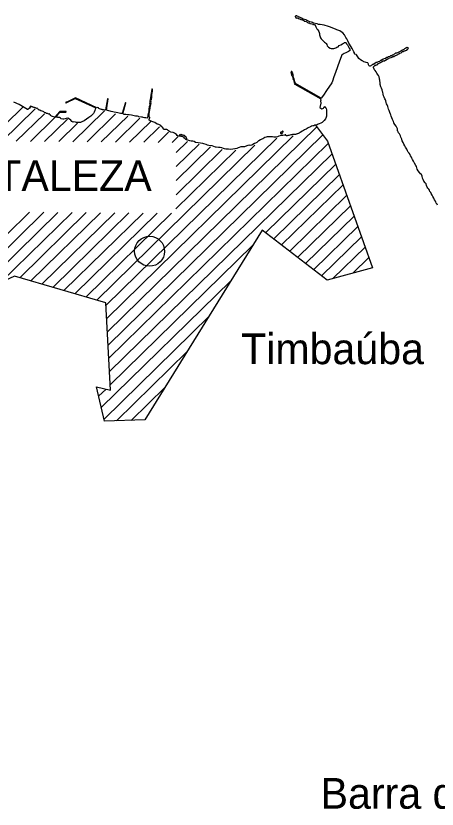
# Model space of a CAD drawing. Extents: x 662444 to 1640468, y 7452018 to 9606170.
# Drawn here: x 1219061 to 1228458, y 9570800 to 9588518 of the extents above; entities that cross this region are included whole.
import ezdxf

# ---------------------------------------------------------------- set-up
doc = ezdxf.new("R2010")
doc.units = 0
for name, color, linetype in [('Level 1', 7, 'Continuous'), ('Level 2', 7, 'Continuous'), ('Level 3', 7, 'Continuous')]:
    doc.layers.add(name, color=color, linetype=linetype)

msp = doc.modelspace()

# ---------------------------------------------------------------- linework, layer by layer
at = {"layer": 'Level 1'}
for points in [[(1225745, 9586079), (1226012, 9585722), (1227015, 9582889), (1226007, 9582614), (1224558, 9583735), (1221937, 9579492), (1221037, 9579467), (1220858, 9580229), (1221173, 9580161), (1221071, 9582105), (1219032, 9582704), (1218218, 9582331), (1216260, 9583731), (1213112, 9582624), (1212367, 9583519), (1212654, 9583962), (1212769, 9587547), (1215230, 9588504)], [(1227631, 9587725), (1227604, 9587708), (1227587, 9587700), (1227574, 9587695), (1227550, 9587683), (1227529, 9587682), (1227516, 9587668), (1227500, 9587662), (1227480, 9587643), (1227460, 9587642), (1227440, 9587625), (1227419, 9587624), (1227402, 9587608), (1227374, 9587603), (1227351, 9587588), (1227334, 9587587), (1227305, 9587567), (1227272, 9587560), (1227264, 9587548), (1227236, 9587541), (1227209, 9587524), (1227197, 9587521), (1227169, 9587500), (1227143, 9587495), (1227114, 9587476), (1227092, 9587473), (1227068, 9587454), (1227053, 9587454), (1227037, 9587435), (1227013, 9587432), (1227003, 9587418), (1226987, 9587406), (1226976, 9587405), (1226964, 9587396), (1226958, 9587398), (1226944, 9587400), (1226935, 9587413), (1226930, 9587427), (1226927, 9587441), (1226921, 9587452), (1226909, 9587466), (1226872, 9587478), (1226851, 9587484), (1226826, 9587489), (1226813, 9587497), (1226786, 9587511), (1226751, 9587533), (1226712, 9587564), (1226688, 9587604), (1226674, 9587629), (1226662, 9587648), (1226649, 9587658), (1226621, 9587666), (1226617, 9587672), (1226612, 9587693), (1226599, 9587714), (1226584, 9587746), (1226562, 9587788), (1226544, 9587827), (1226489, 9587909), (1226466, 9587960), (1226447, 9588002), (1226420, 9588033), (1226409, 9588064), (1226391, 9588094), (1226356, 9588140), (1226317, 9588165), (1226284, 9588185), (1226220, 9588210), (1226190, 9588219), (1226135, 9588244), (1226083, 9588268), (1226038, 9588283), (1225939, 9588312), (1225852, 9588327), (1225814, 9588329), (1225781, 9588337), (1225703, 9588356), (1225676, 9588368), (1225653, 9588376), (1225618, 9588388), (1225575, 9588406), (1225553, 9588416), (1225528, 9588429), (1225500, 9588440), (1225472, 9588446), (1225433, 9588467), (1225415, 9588471), (1225391, 9588490), (1225372, 9588493), (1225356, 9588506), (1225338, 9588508), (1225326, 9588517), (1225315, 9588516), (1225309, 9588518), (1225297, 9588515), (1225298, 9588512), (1225291, 9588507), (1225291, 9588500), (1225295, 9588498), (1225295, 9588486)], [(1225295, 9588486), (1225301, 9588486), (1225308, 9588476), (1225318, 9588478), (1225330, 9588470), (1225344, 9588471), (1225364, 9588457), (1225386, 9588454), (1225401, 9588443), (1225408, 9588443), (1225421, 9588435), (1225427, 9588436), (1225445, 9588427), (1225456, 9588428), (1225469, 9588423), (1225482, 9588415), (1225495, 9588401), (1225506, 9588400), (1225533, 9588389), (1225551, 9588383), (1225565, 9588373), (1225582, 9588366), (1225601, 9588364), (1225626, 9588345), (1225635, 9588347), (1225661, 9588339), (1225685, 9588335), (1225695, 9588321), (1225703, 9588324), (1225716, 9588317), (1225725, 9588322), (1225735, 9588321), (1225740, 9588310), (1225744, 9588292), (1225750, 9588275), (1225765, 9588244), (1225778, 9588231), (1225800, 9588210), (1225819, 9588172), (1225830, 9588148), (1225832, 9588123), (1225835, 9588097), (1225840, 9588072), (1225847, 9588049), (1225857, 9588026), (1225870, 9588006), (1225892, 9587982), (1225907, 9587971), (1225926, 9587956), (1225949, 9587928), (1225966, 9587916), (1225984, 9587899), (1225998, 9587878), (1226006, 9587851), (1226032, 9587817), (1226072, 9587794), (1226093, 9587786), (1226123, 9587786), (1226152, 9587790), (1226178, 9587797), (1226195, 9587806), (1226219, 9587816), (1226254, 9587830), (1226269, 9587855), (1226311, 9587875), (1226345, 9587894), (1226365, 9587904), (1226374, 9587912), (1226392, 9587922), (1226412, 9587926), (1226426, 9587915), (1226438, 9587895), (1226455, 9587870), (1226471, 9587843), (1226480, 9587827), (1226498, 9587798), (1226511, 9587774), (1226518, 9587762), (1226520, 9587750), (1226506, 9587736), (1226482, 9587719), (1226454, 9587705), (1226419, 9587690), (1226382, 9587675), (1226363, 9587663), (1226345, 9587656), (1226335, 9587647), (1226328, 9587627), (1226318, 9587601), (1226280, 9587504), (1226232, 9587377), (1226190, 9587251), (1226153, 9587153), (1226122, 9587062), (1226109, 9587019), (1225987, 9586848), (1225922, 9586749), (1225870, 9586681), (1225299, 9587006), (1225299, 9587005), (1225297, 9587015)], [(1227435, 9586280), (1227427, 9586305), (1227418, 9586326), (1227402, 9586363), (1227386, 9586402), (1227372, 9586438), (1227363, 9586466), (1227356, 9586492), (1227342, 9586530), (1227332, 9586557), (1227318, 9586584), (1227312, 9586621), (1227303, 9586642), (1227293, 9586668), (1227277, 9586706), (1227265, 9586731), (1227257, 9586773), (1227245, 9586811), (1227240, 9586832), (1227233, 9586863), (1227216, 9586900), (1227204, 9586936), (1227188, 9586989), (1227186, 9587016), (1227178, 9587079), (1227172, 9587105), (1227169, 9587123), (1227163, 9587153), (1227147, 9587190), (1227126, 9587218), (1227114, 9587239), (1227095, 9587268), (1227075, 9587295), (1227060, 9587312), (1227047, 9587347), (1227039, 9587358), (1227039, 9587381), (1227048, 9587388), (1227065, 9587407), (1227075, 9587410), (1227083, 9587419), (1227098, 9587419), (1227107, 9587429), (1227119, 9587428), (1227132, 9587448), (1227151, 9587451), (1227172, 9587471), (1227196, 9587474), (1227218, 9587493), (1227257, 9587513), (1227285, 9587512), (1227311, 9587539), (1227324, 9587538), (1227353, 9587558), (1227378, 9587564), (1227396, 9587579), (1227434, 9587589), (1227445, 9587595), (1227467, 9587608), (1227489, 9587614), (1227517, 9587629), (1227532, 9587631), (1227552, 9587643), (1227578, 9587653), (1227592, 9587670), (1227609, 9587674), (1227628, 9587686), (1227652, 9587690), (1227686, 9587719), (1227710, 9587722), (1227723, 9587738), (1227743, 9587739), (1227754, 9587748), (1227773, 9587754), (1227781, 9587755), (1227788, 9587756), (1227791, 9587766), (1227799, 9587772), (1227803, 9587778), (1227813, 9587789), (1227816, 9587797), (1227811, 9587796), (1227811, 9587801), (1227810, 9587804), (1227801, 9587809), (1227791, 9587805), (1227788, 9587808), (1227781, 9587810), (1227768, 9587805), (1227767, 9587797), (1227761, 9587797), (1227750, 9587798), (1227745, 9587791), (1227730, 9587784), (1227718, 9587764), (1227699, 9587762), (1227678, 9587747), (1227667, 9587749), (1227649, 9587729), (1227640, 9587729), (1227631, 9587725)], [(1225297, 9587015), (1225293, 9587020), (1225288, 9587021), (1225269, 9587099), (1225272, 9587099), (1225270, 9587116), (1225263, 9587116), (1225244, 9587181), (1225248, 9587187), (1225250, 9587188), (1225253, 9587195), (1225248, 9587203), (1225242, 9587208), (1225236, 9587224), (1225240, 9587226), (1225237, 9587235), (1225225, 9587256), (1225233, 9587258), (1225232, 9587264), (1225223, 9587264), (1225220, 9587274), (1225201, 9587274), (1225202, 9587264), (1225195, 9587262), (1225195, 9587253), (1225201, 9587253), (1225208, 9587231), (1225200, 9587230), (1225201, 9587215), (1225208, 9587218), (1225213, 9587201), (1225210, 9587200), (1225209, 9587187), (1225212, 9587185), (1225218, 9587183), (1225224, 9587183), (1225250, 9587114), (1225242, 9587111), (1225245, 9587098), (1225254, 9587098), (1225276, 9587015), (1225271, 9586999), (1225282, 9586990), (1225287, 9586996), (1225862, 9586663), (1225854, 9586647), (1225860, 9586646), (1225863, 9586642), (1225863, 9586634), (1225864, 9586627), (1225858, 9586623), (1225864, 9586567), (1225841, 9586468), (1225885, 9586445), (1225912, 9586448), (1225920, 9586453), (1225933, 9586471), (1225939, 9586485), (1225942, 9586493), (1225961, 9586475), (1225973, 9586464), (1225984, 9586448), (1225990, 9586418), (1225992, 9586389), (1225993, 9586354), (1225991, 9586315), (1225990, 9586275), (1225985, 9586253), (1225965, 9586215), (1225937, 9586183), (1225893, 9586139), (1225862, 9586124), (1225827, 9586110), (1225806, 9586101), (1225780, 9586087), (1225745, 9586079), (1225726, 9586074), (1225707, 9586064), (1225684, 9586061), (1225659, 9586052), (1225632, 9586038), (1225598, 9586024), (1225582, 9586014), (1225561, 9586002), (1225536, 9585989), (1225500, 9585972), (1225476, 9585958), (1225449, 9585941), (1225421, 9585922), (1225402, 9585910), (1225382, 9585900), (1225365, 9585892), (1225344, 9585886), (1225330, 9585881), (1225320, 9585878), (1225297, 9585868), (1225279, 9585865), (1225259, 9585865), (1225235, 9585865), (1225215, 9585863), (1225197, 9585860)], [(1222418, 9585983), (1222392, 9585980), (1222369, 9585983), (1222357, 9585988), (1222346, 9586011), (1222335, 9586029), (1222320, 9586039), (1222308, 9586049), (1222293, 9586067), (1222250, 9586090), (1222213, 9586100), (1222158, 9586133), (1222119, 9586151), (1222079, 9586166), (1222057, 9586175), (1222037, 9586186), (1222033, 9586199), (1222033, 9586221), (1222039, 9586224), (1222047, 9586238), (1222047, 9586251), (1222038, 9586262), (1222027, 9586268), (1222031, 9586285), (1222032, 9586307), (1222032, 9586327), (1222036, 9586354), (1222040, 9586370), (1222044, 9586403), (1222051, 9586415), (1222052, 9586434), (1222054, 9586456), (1222056, 9586476), (1222060, 9586490), (1222061, 9586505), (1222072, 9586528), (1222069, 9586556), (1222077, 9586574), (1222073, 9586596), (1222078, 9586620), (1222074, 9586634), (1222086, 9586647), (1222087, 9586672), (1222094, 9586685), (1222093, 9586710), (1222095, 9586721), (1222095, 9586746), (1222096, 9586754), (1222097, 9586779), (1222102, 9586796), (1222100, 9586815), (1222106, 9586832), (1222107, 9586848), (1222109, 9586864), (1222111, 9586882), (1222103, 9586882), (1222101, 9586890), (1222091, 9586878), (1222094, 9586859), (1222084, 9586840), (1222089, 9586823), (1222080, 9586800), (1222083, 9586778), (1222072, 9586752), (1222075, 9586735), (1222066, 9586699), (1222067, 9586684), (1222054, 9586654), (1222056, 9586635), (1222051, 9586618), (1222047, 9586571), (1222041, 9586545), (1222049, 9586526), (1222033, 9586495), (1222036, 9586483), (1222031, 9586461), (1222030, 9586444), (1222025, 9586419), (1222028, 9586400), (1222020, 9586375), (1222025, 9586355), (1222016, 9586336), (1222008, 9586325), (1222009, 9586311), (1222002, 9586299), (1222002, 9586280), (1222003, 9586262), (1221995, 9586252), (1221994, 9586241), (1221982, 9586235), (1221962, 9586238), (1221929, 9586240), (1221902, 9586248), (1221883, 9586255), (1221860, 9586254), (1221806, 9586266), (1221798, 9586271), (1221773, 9586277), (1221732, 9586281), (1221701, 9586288), (1221668, 9586291)], [(1219791, 9586324), (1219779, 9586331), (1219769, 9586339), (1219742, 9586339), (1219723, 9586356), (1219705, 9586356), (1219684, 9586375), (1219671, 9586379), (1219649, 9586392), (1219618, 9586394), (1219599, 9586409), (1219577, 9586413), (1219559, 9586433), (1219547, 9586440), (1219540, 9586439), (1219535, 9586453), (1219524, 9586452), (1219516, 9586453), (1219501, 9586465), (1219490, 9586461), (1219477, 9586475), (1219470, 9586475), (1219464, 9586472), (1219461, 9586471), (1219458, 9586475), (1219447, 9586482), (1219437, 9586481), (1219430, 9586489), (1219418, 9586490), (1219414, 9586487), (1219408, 9586495), (1219400, 9586491), (1219396, 9586497), (1219391, 9586498), (1219382, 9586496), (1219374, 9586486), (1219375, 9586483), (1219383, 9586482), (1219383, 9586478), (1219387, 9586470), (1219374, 9586460), (1219362, 9586453), (1219331, 9586430), (1219321, 9586429), (1219136, 9586535), (1219016, 9586594)], [(1221668, 9586291), (1221637, 9586297), (1221589, 9586306), (1221553, 9586310), (1221516, 9586315), (1221500, 9586315), (1221478, 9586316), (1221459, 9586322), (1221452, 9586327), (1221446, 9586333), (1221515, 9586577), (1221503, 9586582), (1221429, 9586335), (1221425, 9586334), (1221398, 9586337), (1221366, 9586346), (1221336, 9586350), (1221297, 9586358), (1221251, 9586368), (1221222, 9586373), (1221187, 9586379), (1221166, 9586386), (1221136, 9586394), (1221112, 9586401), (1221104, 9586404), (1221088, 9586411), (1221079, 9586413), (1221122, 9586662), (1221104, 9586667), (1221060, 9586420), (1221043, 9586415), (1221019, 9586416), (1220995, 9586423), (1220984, 9586427), (1220968, 9586428), (1220948, 9586434), (1220929, 9586442), (1220915, 9586451), (1220902, 9586463), (1220883, 9586468), (1220868, 9586467), (1220390, 9586689), (1220195, 9586591), (1220188, 9586594), (1220178, 9586590), (1220175, 9586581), (1220178, 9586574), (1220184, 9586572), (1220194, 9586576), (1220196, 9586580), (1220386, 9586670), (1220841, 9586462), (1220836, 9586451), (1220831, 9586431), (1220826, 9586401), (1220809, 9586369), (1220790, 9586337), (1220730, 9586277), (1220687, 9586251), (1220639, 9586212), (1220583, 9586175), (1220536, 9586152), (1220503, 9586140), (1220467, 9586139), (1220447, 9586133), (1220414, 9586136), (1220389, 9586145), (1220348, 9586148), (1220332, 9586146), (1220308, 9586161), (1220285, 9586192), (1220257, 9586214), (1220217, 9586233), (1220185, 9586228), (1220157, 9586219), (1220133, 9586213), (1220107, 9586214), (1220074, 9586221), (1220053, 9586234), (1220031, 9586245), (1219998, 9586250), (1219986, 9586257), (1219962, 9586257), (1219951, 9586259), (1220045, 9586364), (1220178, 9586371), (1220180, 9586373), (1220180, 9586379), (1220167, 9586383), (1220133, 9586383), (1220068, 9586382), (1220045, 9586382), (1219933, 9586258), (1219881, 9586268), (1219855, 9586278), (1219846, 9586286), (1219835, 9586292), (1219837, 9586305), (1219818, 9586309), (1219812, 9586328), (1219791, 9586324)], [(1218439, 9585721), (1219213, 9586481)], [(1218755, 9585719), (1219490, 9586440)], [(1220335, 9585707), (1221035, 9586394)], [(1219071, 9585716), (1219699, 9586332)], [(1219388, 9585714), (1219937, 9586253)], [(1219703, 9585712), (1220211, 9586211)], [(1220652, 9585705), (1221287, 9586328)], [(1220967, 9585703), (1221555, 9586280)], [(1221284, 9585700), (1221824, 9586230)], [(1228468, 9584292), (1228456, 9584309), (1228439, 9584333), (1228427, 9584362), (1228420, 9584383), (1228399, 9584410), (1228381, 9584447), (1228365, 9584481), (1228348, 9584514), (1228325, 9584547), (1228315, 9584572), (1228298, 9584598), (1228285, 9584627), (1228273, 9584648), (1228253, 9584671), (1228236, 9584695), (1228218, 9584729), (1228210, 9584764), (1228194, 9584790), (1228163, 9584824), (1228144, 9584865), (1228132, 9584896), (1228127, 9584939), (1228106, 9584972), (1228086, 9584993), (1228061, 9585023), (1228032, 9585056), (1228016, 9585097), (1227995, 9585155), (1227980, 9585177), (1227952, 9585228), (1227931, 9585273), (1227909, 9585307), (1227894, 9585338), (1227883, 9585363), (1227866, 9585391), (1227855, 9585420), (1227835, 9585449), (1227811, 9585477), (1227798, 9585504), (1227779, 9585543), (1227767, 9585566), (1227755, 9585586), (1227739, 9585616), (1227716, 9585651), (1227698, 9585687), (1227680, 9585725), (1227667, 9585761), (1227646, 9585812), (1227638, 9585839), (1227629, 9585865), (1227616, 9585884), (1227595, 9585907), (1227588, 9585925), (1227585, 9585934), (1227575, 9585958), (1227574, 9585959), (1227571, 9585992), (1227558, 9586028), (1227541, 9586054), (1227511, 9586092), (1227495, 9586129), (1227484, 9586156), (1227465, 9586202), (1227445, 9586243), (1227435, 9586280)], [(1220019, 9585709), (1220435, 9586118)], [(1221105, 9581464), (1225773, 9586042)], [(1221599, 9585698), (1222069, 9586158)], [(1221916, 9585695), (1222265, 9586039)], [(1221121, 9581166), (1225907, 9585861)], [(1222232, 9585693), (1222467, 9585924)], [(1225197, 9585860), (1225173, 9585854), (1225150, 9585849), (1225131, 9585843), (1225111, 9585842), (1225097, 9585842), (1225085, 9585848), (1225081, 9585858), (1225071, 9585861), (1225053, 9585856), (1225016, 9585849), (1224987, 9585845), (1224954, 9585841), (1224930, 9585829), (1224911, 9585823), (1224895, 9585818), (1224869, 9585812), (1224847, 9585811), (1224832, 9585810), (1224812, 9585812), (1224783, 9585814), (1224747, 9585817), (1224723, 9585817), (1224695, 9585815), (1224664, 9585813), (1224644, 9585809), (1224614, 9585799), (1224592, 9585787), (1224570, 9585771), (1224546, 9585763), (1224517, 9585751), (1224478, 9585729), (1224466, 9585716), (1224437, 9585690), (1224407, 9585673), (1224384, 9585664), (1224344, 9585642), (1224325, 9585633), (1224290, 9585626), (1224268, 9585627), (1224237, 9585620), (1224216, 9585614), (1224163, 9585596), (1224135, 9585595), (1224103, 9585590), (1224078, 9585590), (1224044, 9585577), (1224020, 9585571), (1223988, 9585553), (1223945, 9585546), (1223899, 9585539), (1223853, 9585535), (1223805, 9585538), (1223748, 9585540), (1223716, 9585550), (1223691, 9585556), (1223658, 9585568), (1223617, 9585575), (1223582, 9585579), (1223531, 9585584), (1223515, 9585585), (1223478, 9585602), (1223436, 9585614), (1223364, 9585623), (1223338, 9585632), (1223306, 9585645), (1223253, 9585663), (1223228, 9585667), (1223179, 9585676), (1223128, 9585682), (1223067, 9585691), (1223041, 9585710), (1223009, 9585716), (1222970, 9585723), (1222943, 9585727), (1222895, 9585740), (1222878, 9585748), (1222852, 9585760), (1222837, 9585775), (1222820, 9585786), (1222804, 9585809), (1222785, 9585815), (1222765, 9585822), (1222749, 9585826), (1222747, 9585826), (1222739, 9585826), (1222699, 9585830), (1222682, 9585833), (1222661, 9585847), (1222642, 9585870), (1222624, 9585887), (1222596, 9585900), (1222566, 9585910), (1222515, 9585920), (1222500, 9585925), (1222486, 9585934), (1222464, 9585953), (1222448, 9585965), (1222440, 9585976), (1222428, 9585983), (1222418, 9585983)], [(1222852, 9585760), (1222873, 9585768), (1222876, 9585786), (1222864, 9585785), (1222863, 9585808), (1222851, 9585823), (1222839, 9585820), (1222833, 9585843), (1222815, 9585839), (1222806, 9585854), (1222785, 9585848), (1222763, 9585867), (1222744, 9585857), (1222722, 9585867), (1222708, 9585857), (1222717, 9585855), (1222713, 9585845), (1222720, 9585844), (1222699, 9585830)], [(1225019, 9585921), (1225023, 9585927), (1225021, 9585931), (1225021, 9585938), (1225015, 9585944), (1225010, 9585944), (1224998, 9585939), (1224988, 9585923), (1224971, 9585923), (1224964, 9585912), (1224961, 9585899), (1224969, 9585891), (1224973, 9585885), (1224981, 9585881), (1224990, 9585888), (1225003, 9585890), (1225011, 9585908), (1225019, 9585921)], [(1221074, 9582058), (1224879, 9585790)], [(1221089, 9581761), (1225243, 9585835)], [(1221136, 9580870), (1226031, 9585670)], [(1222548, 9585691), (1222673, 9585813)], [(1222640, 9585468), (1222890, 9585714)], [(1220864, 9582165), (1224395, 9585628)], [(1222630, 9584210), (1223964, 9585518)], [(1222633, 9584524), (1223663, 9585534)], [(1222635, 9584840), (1223403, 9585593)], [(1222637, 9585153), (1223147, 9585653)], [(1221152, 9580573), (1226113, 9585438)], [(1224634, 9583676), (1226195, 9585206)], [(1224812, 9583539), (1226277, 9584974)], [(1224990, 9583401), (1226359, 9584742)], [(1225169, 9583262), (1226441, 9584510)], [(1225347, 9583125), (1226523, 9584278)], [(1217820, 9582615), (1219368, 9584134)], [(1218005, 9582483), (1219685, 9584131)], [(1218188, 9582352), (1220000, 9584129)], [(1218719, 9582560), (1220316, 9584127)], [(1219149, 9582670), (1220632, 9584124)], [(1219395, 9582598), (1220949, 9584122)], [(1219639, 9582526), (1221265, 9584120)], [(1219884, 9582454), (1221581, 9584117)], [(1220129, 9582381), (1221897, 9584115)], [(1220375, 9582309), (1222214, 9584113)], [(1220619, 9582237), (1222529, 9584110)], [(1225524, 9582987), (1226605, 9584047)], [(1225702, 9582849), (1226687, 9583815)], [(1225881, 9582712), (1226769, 9583583)], [(1221168, 9580276), (1224347, 9583394)], [(1226135, 9582649), (1226852, 9583351)], [(1226577, 9582770), (1226934, 9583119)], [(1220967, 9579767), (1223858, 9582602)], [(1221027, 9579513), (1223370, 9581811)], [(1221306, 9579474), (1222881, 9581019)], [(1220906, 9580021), (1221073, 9580183)], [(1221633, 9579484), (1222392, 9580227)]]:
    msp.add_lwpolyline(points, dxfattribs=at)
at = {"layer": 'Level 2'}
msp.add_ellipse((1222044, 9583260), major_axis=(334, -2), ratio=0.999997, dxfattribs=at)

# ---------------------------------------------------------------- texts
at = {"layer": 'Level 3'}
for s, height, p in [('FORTALEZA', 686, (1216688, 9584607)), ('Timbaúba', 686, (1224085, 9580739)), ('Barra do Pacoti', 685.99, (1225859, 9570809))]:
    msp.add_text(s, height=height, dxfattribs=at).set_placement(p)

doc.saveas('drawing.dxf')
